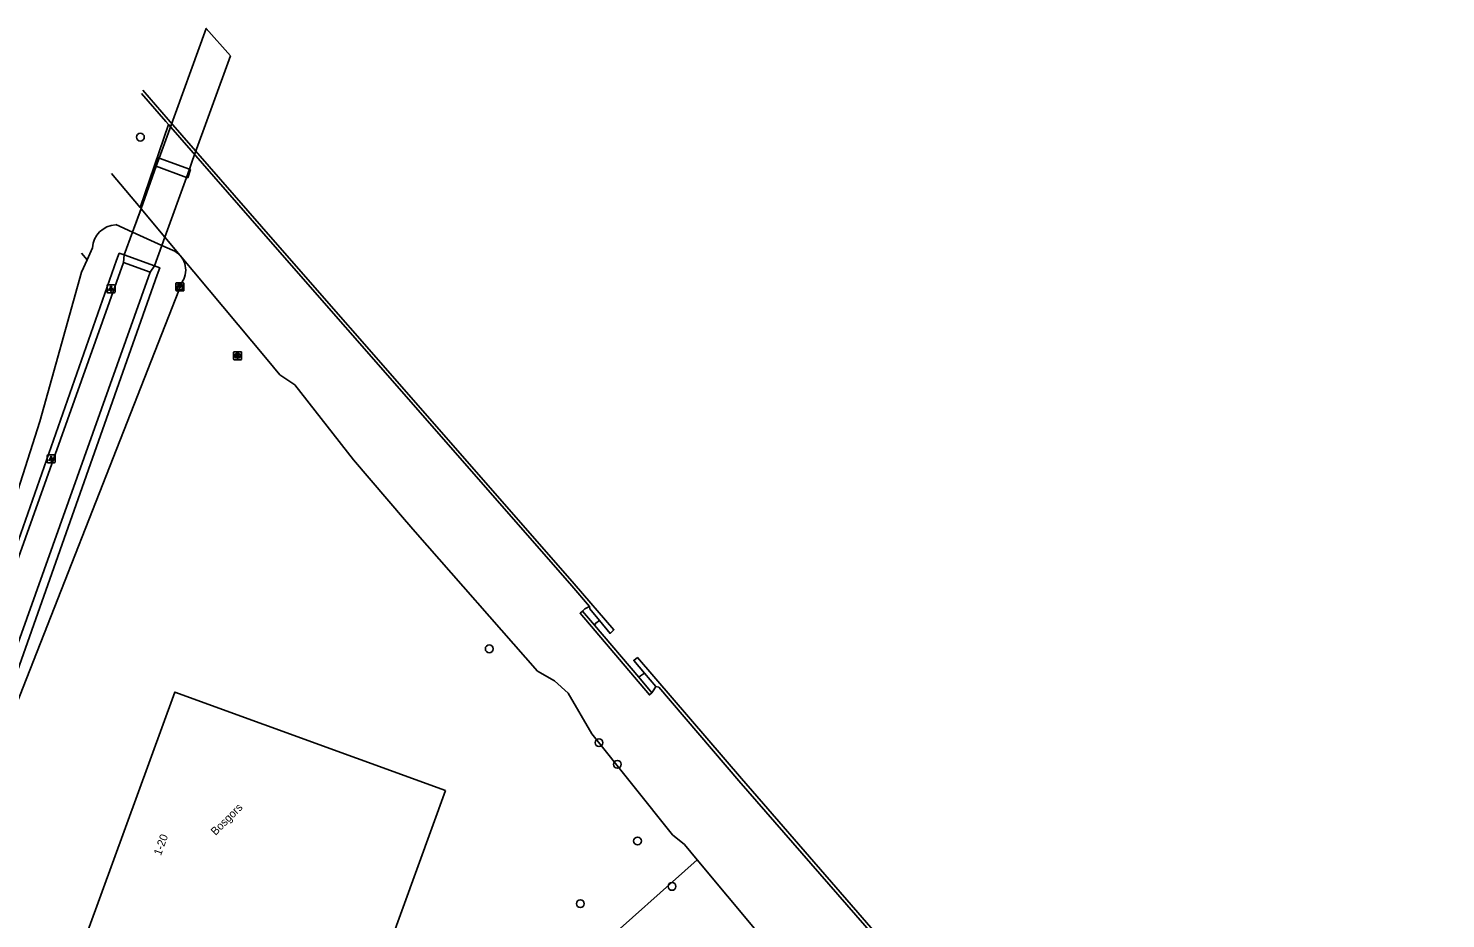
# Model space of a CAD drawing. Extents: x 156664 to 157568, y 383571 to 384421.
# Drawn here: x 156849.9 to 157027, y 384310 to 384421.3 of the extents above; entities that cross this region are included whole.
import ezdxf

# ---------------------------------------------------------------- set-up
doc = ezdxf.new("R2010")
doc.units = 0
for name, color, linetype in [('IMGEO_Boom', 7, 'Continuous'), ('IMGEO_Dek', 7, 'Continuous'), ('IMGEO_Fietspad_open', 7, 'Continuous'), ('IMGEO_Gemengd_bos', 7, 'Continuous'), ('IMGEO_Groenvoorziening', 7, 'Continuous'), ('IMGEO_Hek', 7, 'Continuous'), ('IMGEO_Houtwal', 7, 'Continuous'), ('IMGEO_Kademuur', 7, 'Continuous'), ('IMGEO_Kast', 7, 'Continuous'), ('IMGEO_Lichtpunt', 7, 'Continuous'), ('IMGEO_Loofbos', 7, 'Continuous'), ('IMGEO_Openbare_ruimte_label', 7, 'Continuous'), ('IMGEO_Pand', 7, 'Continuous'), ('IMGEO_Pand_nummerreeks', 7, 'Continuous'), ('IMGEO_Pijler', 7, 'Continuous'), ('IMGEO_Rioolput', 7, 'Continuous'), ('IMGEO_Waterloop', 7, 'Continuous')]:
    doc.layers.add(name, color=color, linetype=linetype)

msp = doc.modelspace()

# ---------------------------------------------------------------- linework, layer by layer
at = {"layer": 'IMGEO_Boom'}
for centre in [(156863.91, 384407.68), (156907.51, 384343.72), (156921.23, 384331.99), (156923.52, 384329.29), (156926.04, 384319.71), (156930.34, 384314.03), (156918.89, 384311.87)]:
    msp.add_circle(centre, 0.489, dxfattribs=at)
at = {"layer": 'IMGEO_Dek'}
msp.add_lwpolyline([(156875.15, 384417.82), (156872.14, 384421.27), (156867.44, 384408.27), (156866.27, 384405.03), (156865.9, 384404.04), (156863.99, 384398.74), (156862.92, 384395.79), (156861.89, 384392.95), (156861.79, 384391.99), (156865.12, 384390.79), (156865.67, 384391.6), (156866.59, 384394.15), (156866.96, 384395.19), (156869.67, 384402.65), (156870.04, 384403.68), (156870.44, 384404.8)], close=True, dxfattribs=at)
at = {"layer": 'IMGEO_Fietspad_open'}
msp.add_lwpolyline([(156835.74, 384318.86), (156861.79, 384391.99), (156865.12, 384390.79), (156837.53, 384313.35)], dxfattribs=at)
at = {"layer": 'IMGEO_Gemengd_bos'}
for points in [[(156864.01, 384398.72), (156862.92, 384395.79)], [(156864.01, 384398.72), (156863.99, 384398.74), (156863.88, 384398.87)], [(156860.82, 384396.74), (156862.92, 384395.79)], [(156857.24, 384392.35), (156856.56, 384393.19)], [(156857.24, 384392.35), (156857.91, 384393.84)]]:
    msp.add_lwpolyline(points, dxfattribs=at)
msp.add_arc((156861.02, 384393.62), 3.12, 93.7377, 175.9662, dxfattribs=at)
at = {"layer": 'IMGEO_Groenvoorziening'}
for points in [[(156862.92, 384395.79), (156862.92, 384395.79), (156866.59, 384394.15), (156867.93, 384393.54)], [(156869.19, 384389.66), (156843.61, 384324.6), (156841.61, 384321.1), (156844.98, 384330.95), (156866, 384390.47), (156866.32, 384391.36), (156865.67, 384391.6), (156861.89, 384392.95), (156861.26, 384393.17), (156860.94, 384392.3), (156844.84, 384346.47), (156838.78, 384329.6), (156836.54, 384325.29), (156837.99, 384330.3), (156851.36, 384372.13), (156856.55, 384390.8), (156857.24, 384392.35)]]:
    msp.add_lwpolyline(points, dxfattribs=at)
msp.add_arc((156866.88, 384391.06), 2.7, 328.804, 67.0801, dxfattribs=at)
at = {"layer": 'IMGEO_Hek'}
for points in [[(156867.44, 384408.27), (156872.14, 384421.27)], [(156875.15, 384417.82), (156870.44, 384404.8)], [(156867.44, 384408.27), (156866.27, 384405.03)], [(156866.27, 384405.03), (156865.9, 384404.04)], [(156870.04, 384403.68), (156870.44, 384404.8)], [(156865.9, 384404.04), (156863.99, 384398.74)], [(156869.67, 384402.65), (156870.04, 384403.68)], [(156866.96, 384395.19), (156869.67, 384402.65)], [(156863.99, 384398.74), (156862.92, 384395.79)], [(156862.92, 384395.79), (156861.89, 384392.95)], [(156865.67, 384391.6), (156866.59, 384394.15)], [(156866.59, 384394.15), (156866.96, 384395.19)], [(156861.89, 384392.95), (156861.79, 384391.99)], [(156865.12, 384390.79), (156865.67, 384391.6)]]:
    msp.add_lwpolyline(points, dxfattribs=at)
at = {"layer": 'IMGEO_Houtwal'}
for points in [[(156865.9, 384404.04), (156865.78, 384404.08), (156866.13, 384405.08), (156866.27, 384405.03), (156870.04, 384403.68), (156870.17, 384403.63), (156869.83, 384402.6), (156869.67, 384402.65), (156865.9, 384404.04)], [(156933.49, 384317.37), (156931.89, 384319.27), (156930.43, 384320.47), (156920.32, 384333.08), (156917.35, 384338.18), (156915.68, 384339.71), (156913.54, 384340.93), (156898.26, 384358.33), (156896.92, 384359.9), (156890.54, 384367.33), (156883.2, 384376.71), (156881.32, 384377.98), (156879.76, 384379.88), (156866.96, 384395.19), (156864.01, 384398.72)], [(156920.02, 384349.03), (156919.46, 384348.73), (156919.18, 384348.44)], [(156927.83, 384338.23), (156928.08, 384338.61), (156928.32, 384339.01)]]:
    msp.add_lwpolyline(points, dxfattribs=at)
at = {"layer": 'IMGEO_Kademuur'}
for points in [[(156867.42, 384409.25), (156867.1, 384409.62), (156864.05, 384413.13)], [(156921.28, 384347.25), (156922.61, 384345.65), (156923.08, 384346.1), (156918.13, 384351.86), (156899.21, 384373.46), (156880.76, 384394.54), (156867.4, 384409.88), (156864.21, 384413.56)], [(156867.42, 384409.25), (156880.46, 384394.28), (156898.91, 384373.2), (156917.83, 384351.59), (156920.02, 384349.03)], [(156919.18, 384348.44), (156918.87, 384348.18), (156927.53, 384337.97), (156927.83, 384338.23)], [(156920.67, 384346.67), (156919.18, 384348.44)], [(156920.02, 384349.03), (156920.06, 384348.72), (156921.28, 384347.25)], [(156920.67, 384346.67), (156926.19, 384340.17)], [(156926.89, 384340.7), (156925.56, 384342.27), (156926.02, 384342.63), (156939.02, 384327.5), (156962.6, 384300.36), (156983.82, 384276.03), (156992.33, 384266.34), (156993.04, 384263.6), (157006.31, 384248.53), (157023.85, 384228.32), (157027.04, 384224.69), (157026.74, 384224.43), (157025.56, 384225.77)], [(156927.83, 384338.23), (156926.19, 384340.17)], [(156928.32, 384339.01), (156926.89, 384340.7)], [(156928.32, 384339.01), (156928.69, 384338.92), (156938.72, 384327.24), (156962.3, 384300.1), (156983.52, 384275.77), (156991.97, 384266.15), (156992.67, 384263.41), (157006.01, 384248.27), (157023.54, 384228.05), (157023.76, 384227.8)]]:
    msp.add_lwpolyline(points, dxfattribs=at)
at = {"layer": 'IMGEO_Kast'}
for p, q in [((156868.35, 384388.53), (156868.35, 384389.37)), ((156868.35, 384389.37), (156868.35, 384388.53)), ((156868.43, 384389.45), (156869.27, 384389.45)), ((156869.27, 384389.45), (156868.43, 384389.45)), ((156869.35, 384389.38), (156869.35, 384388.54)), ((156869.35, 384388.54), (156869.35, 384389.38)), ((156869.28, 384388.46), (156868.44, 384388.46)), ((156868.44, 384388.46), (156869.28, 384388.46))]:
    msp.add_line(p, q, dxfattribs=at)
for points in [[(156868.55, 384389.25), (156869.15, 384389.25), (156869.15, 384389.16), (156868.55, 384389.16), (156868.55, 384389.25)], [(156868.55, 384389.07), (156869.15, 384389.07), (156869.15, 384388.58), (156868.55, 384388.58), (156868.55, 384389.07)]]:
    msp.add_lwpolyline(points, dxfattribs=at)
msp.add_circle((156868.63, 384388.92), 0.0377, dxfattribs=at)
for centre, start, end in [((156868.43, 384389.38), 92.4484, 184.2845), ((156868.43, 384389.38), 92.4484, 184.2845), ((156869.27, 384389.38), 2.4484, 94.2845), ((156869.27, 384389.38), 2.4484, 94.2845), ((156868.43, 384388.53), 182.4484, 274.2845), ((156868.43, 384388.53), 182.4484, 274.2845), ((156869.27, 384388.53), 272.4484, 4.2845), ((156869.27, 384388.53), 272.4484, 4.2845)]:
    msp.add_arc(centre, 0.0779, start, end, dxfattribs=at)
at = {"layer": 'IMGEO_Lichtpunt'}
for p, q in [((156859.74, 384389.12), (156859.74, 384388.32)), ((156859.74, 384389.12), (156859.74, 384388.32)), ((156860.64, 384389.22), (156859.83, 384389.22)), ((156860.64, 384389.22), (156859.83, 384389.22)), ((156860.74, 384388.32), (156860.74, 384389.12)), ((156860.74, 384388.32), (156860.74, 384389.12)), ((156859.83, 384388.22), (156860.64, 384388.22)), ((156859.83, 384388.22), (156860.64, 384388.22)), ((156852.26, 384367.87), (156852.26, 384367.06)), ((156852.26, 384367.87), (156852.26, 384367.06)), ((156853.17, 384367.96), (156852.36, 384367.96)), ((156853.17, 384367.96), (156852.36, 384367.96)), ((156853.26, 384367.06), (156853.26, 384367.87)), ((156853.26, 384367.06), (156853.26, 384367.87)), ((156852.36, 384366.96), (156853.17, 384366.96)), ((156852.36, 384366.96), (156853.17, 384366.96))]:
    msp.add_line(p, q, dxfattribs=at)
for points in [[(156860.11, 384388.79), (156860.15, 384388.76), (156859.96, 384388.5), (156859.93, 384388.52), (156860.11, 384388.79)], [(156860.21, 384388.74), (156860.26, 384388.74), (156860.26, 384388.42), (156860.21, 384388.42), (156860.21, 384388.74)], [(156860.32, 384388.76), (156860.36, 384388.79), (156860.55, 384388.52), (156860.51, 384388.5), (156860.32, 384388.76)], [(156852.64, 384367.53), (156852.68, 384367.5), (156852.49, 384367.24), (156852.45, 384367.27), (156852.64, 384367.53)], [(156852.74, 384367.48), (156852.79, 384367.48), (156852.79, 384367.16), (156852.74, 384367.16), (156852.74, 384367.48)], [(156852.85, 384367.5), (156852.89, 384367.53), (156853.08, 384367.27), (156853.04, 384367.24), (156852.85, 384367.5)]]:
    msp.add_lwpolyline(points, dxfattribs=at)
for centre in [(156860.24, 384388.92), (156852.76, 384367.66)]:
    msp.add_circle(centre, 0.0994, dxfattribs=at)
for centre, start, end in [((156859.83, 384389.12), 90, 180), ((156859.83, 384389.12), 90, 180), ((156860.64, 384389.12), 0, 90), ((156860.64, 384389.12), 0, 90), ((156859.83, 384388.32), 180, 270), ((156859.83, 384388.32), 180, 270), ((156860.64, 384388.32), 270, 0), ((156860.64, 384388.32), 270, 360), ((156852.36, 384367.87), 90, 180), ((156852.36, 384367.87), 90, 180), ((156853.17, 384367.87), 0, 90), ((156853.17, 384367.87), 0, 90), ((156852.36, 384367.06), 180, 270), ((156852.36, 384367.06), 180, 270), ((156853.17, 384367.06), 270, 0), ((156853.17, 384367.06), 270, 360)]:
    msp.add_arc(centre, 0.0946, start, end, dxfattribs=at)
at = {"layer": 'IMGEO_Loofbos'}
for points in [[(156863.88, 384398.87), (156867.42, 384409.25)], [(156860.3, 384403.15), (156863.88, 384398.87)], [(156920.78, 384306.03), (156933.49, 384317.37)], [(156933.49, 384317.37), (156941.08, 384308.28), (156959.02, 384287.93), (156962.79, 384283.9), (156964.73, 384281.22), (156967.39, 384278.64), (156975.02, 384271.25), (156978.62, 384265.56)]]:
    msp.add_lwpolyline(points, dxfattribs=at)
at = {"layer": 'IMGEO_Pand'}
msp.add_lwpolyline([(156902.06, 384326.02), (156889.74, 384292.16), (156855.89, 384304.48), (156868.2, 384338.32), (156902.06, 384326.02)], dxfattribs=at)
at = {"layer": 'IMGEO_Pijler'}
msp.add_lwpolyline([(156866.27, 384405.03), (156866.13, 384405.08), (156865.78, 384404.08), (156865.9, 384404.04), (156869.67, 384402.65), (156869.83, 384402.6), (156870.17, 384403.63), (156870.04, 384403.68)], close=True, dxfattribs=at)
at = {"layer": 'IMGEO_Rioolput'}
for p, q in [((156875.56, 384379.93), (156875.56, 384380.78)), ((156875.63, 384380.85), (156876.48, 384380.85)), ((156876.04, 384380.63), (156876.07, 384380.63)), ((156876.07, 384380.07), (156876.04, 384380.07)), ((156876.56, 384380.78), (156876.56, 384379.93)), ((156876.48, 384379.85), (156875.63, 384379.85))]:
    msp.add_line(p, q, dxfattribs=at)
for points in [[(156875.56, 384379.93), (156875.56, 384380.78)], [(156875.63, 384380.85), (156876.48, 384380.85)], [(156876.14, 384380.55), (156875.89, 384380.55), (156875.89, 384380.15)], [(156875.89, 384380.15), (156876.02, 384380.15), (156876.02, 384380.32), (156876.03, 384380.32)], [(156876.07, 384380.47), (156876.02, 384380.47), (156876.02, 384380.39)], [(156876.02, 384380.39), (156876.07, 384380.39)], [(156876.07, 384380.29), (156876.15, 384380.15), (156876.28, 384380.15), (156876.22, 384380.28)], [(156876.56, 384380.78), (156876.56, 384379.93)], [(156876.48, 384379.85), (156875.63, 384379.85)]]:
    msp.add_lwpolyline(points, dxfattribs=at)
for centre, radius, start, end in [((156875.63, 384380.78), 0.0765, 91.552, 178.448), ((156875.63, 384380.78), 0.0765, 91.552, 178.448), ((156876.03, 384380.26), 0.0533, 26.0293, 88.6989), ((156876.08, 384380.38), 0.0964, 77.0061, 93.1865), ((156876.05, 384380.58), 0.19, 274.7715, 282.9687), ((156876.09, 384380.43), 0.0378, 276.6634, 79.6772), ((156876.14, 384380.44), 0.109, 350.3612, 89.416), ((156876.14, 384380.44), 0.112, 277.5842, 350.9817), ((156876.13, 384380.23), 0.108, 29.5134, 73.7905), ((156876.48, 384380.78), 0.0765, 1.552, 88.448), ((156876.48, 384380.78), 0.0765, 1.552, 88.448), ((156875.63, 384379.93), 0.0765, 181.552, 268.448), ((156875.63, 384379.93), 0.0765, 181.552, 268.448), ((156876.48, 384379.93), 0.0765, 271.552, 358.448), ((156876.48, 384379.93), 0.0765, 271.552, 358.448)]:
    msp.add_arc(centre, radius, start, end, dxfattribs=at)
for centre, major_axis, ratio, start_param, end_param in [((156876.04, 384380.35), (-0.387, 0.002), 0.722429, 4.712389, 7.853982), ((156876.07, 384380.35), (-0.39, 0.002), 0.717154, 1.570796, 4.712389)]:
    msp.add_ellipse(centre, major_axis=major_axis, ratio=ratio, start_param=start_param, end_param=end_param, dxfattribs=at)
at = {"layer": 'IMGEO_Waterloop'}
for points in [[(156921.28, 384347.25), (156920.82, 384346.94), (156920.67, 384346.67)], [(156926.19, 384340.17), (156926.43, 384340.35), (156926.89, 384340.7)]]:
    msp.add_lwpolyline(points, dxfattribs=at)

# ---------------------------------------------------------------- texts
at = {"layer": 'IMGEO_Openbare_ruimte_label'}
msp.add_text('Bosgors', height=1, rotation=45, dxfattribs=at).set_placement((156873.3, 384320.34))
at = {"layer": 'IMGEO_Pand_nummerreeks'}
msp.add_text('1-20', height=1, rotation=70.0154, dxfattribs=at).set_placement((156866.47, 384317.82))

doc.saveas('drawing.dxf')
